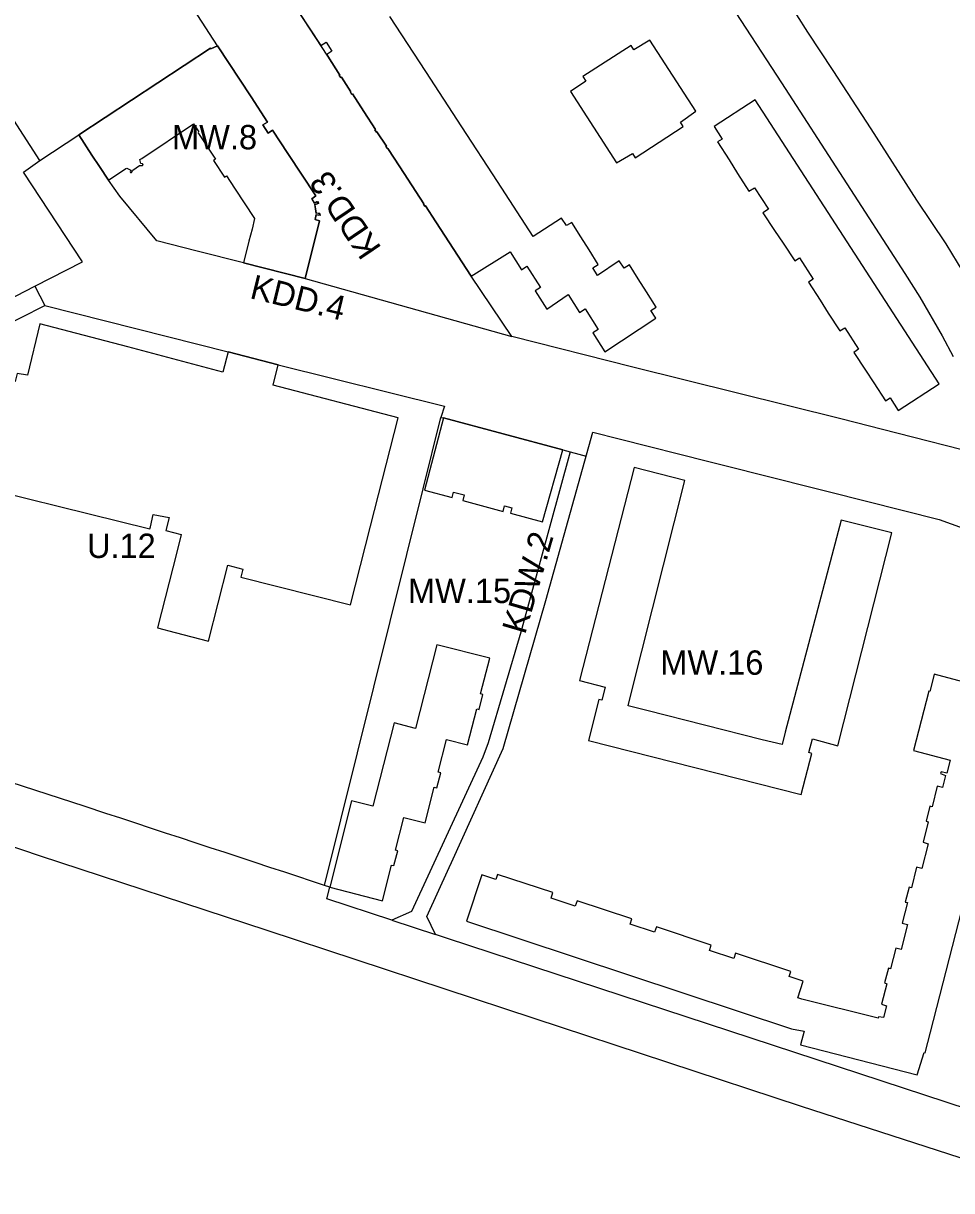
# Model space of a CAD drawing. Extents: x 7424052 to 7425705, y 5546602 to 5547569.
# Drawn here: x 7424865.9 to 7425056.7, y 5546961.1 to 5547200.9 of the extents above; entities that cross this region are included whole.
import ezdxf

# ---------------------------------------------------------------- set-up
doc = ezdxf.new("R2010")
doc.units = 0
for name, color, linetype in [('linie rozgraniczające', 7, 'Continuous'), ('nieprzekraczalne linie zabudowy', 7, 'Continuous'), ('obowiazujace linie zabudowy', 7, 'Continuous'), ('przeznaczenia terenów', 7, 'Continuous')]:
    doc.layers.add(name, color=color, linetype=linetype)

msp = doc.modelspace()

# ---------------------------------------------------------------- linework, layer by layer
at = {"layer": 'linie rozgraniczające'}
for p, q in [((7424905.84, 5547196.33), (7424884.42, 5547229.37)), ((7425007.07, 5547211.22), (7425021.71, 5547188.75)), ((7424869.3, 5547172.76), (7424848.08, 5547205.67)), ((7425027.13, 5547199.15), (7425022.42, 5547206.57)), ((7424928.48, 5547194.19), (7424921.08, 5547205.48)), ((7425032.34, 5547191.28), (7425027.13, 5547199.15)), ((7424904.48, 5547195.74), (7424905.84, 5547196.33)), ((7424905.84, 5547196.33), (7424912.72, 5547185.82)), ((7424877.35, 5547178.06), (7424904.39, 5547195.87)), ((7424904.39, 5547195.87), (7424904.48, 5547195.74)), ((7424930.98, 5547190.33), (7424928.48, 5547194.19)), ((7425040.11, 5547179.28), (7425032.34, 5547191.28)), ((7424930.85, 5547190.24), (7424930.98, 5547190.33)), ((7424931.15, 5547189.8), (7424930.85, 5547190.24)), ((7424931.28, 5547189.88), (7424931.15, 5547189.8)), ((7424933.25, 5547186.87), (7424931.28, 5547189.88)), ((7425021.71, 5547188.75), (7425047.04, 5547149.57)), ((7424933.13, 5547186.79), (7424933.25, 5547186.87)), ((7424933.43, 5547186.35), (7424933.13, 5547186.79)), ((7424933.54, 5547186.43), (7424933.43, 5547186.35)), ((7424935.91, 5547182.81), (7424933.54, 5547186.43)), ((7424912.72, 5547185.82), (7424916.07, 5547180.66)), ((7424938.28, 5547179.14), (7424935.91, 5547182.81)), ((7424916.07, 5547180.66), (7424915.16, 5547180.07)), ((7424915.16, 5547180.07), (7424916.2, 5547178.41)), ((7424938.18, 5547179.06), (7424938.28, 5547179.14)), ((7425049.53, 5547164.65), (7425040.11, 5547179.28)), ((7424869.3, 5547172.76), (7424877.35, 5547178.06)), ((7424880.02, 5547173.83), (7424877.35, 5547178.06)), ((7424916.2, 5547178.41), (7424917.12, 5547179.01)), ((7424917.12, 5547179.01), (7424920.28, 5547174.17)), ((7424938.51, 5547178.6), (7424938.18, 5547179.06)), ((7424938.59, 5547178.67), (7424938.51, 5547178.6)), ((7424940.54, 5547175.72), (7424938.59, 5547178.67)), ((7424940.44, 5547175.65), (7424940.54, 5547175.72)), ((7424940.72, 5547175.2), (7424940.44, 5547175.65)), ((7424940.84, 5547175.26), (7424940.72, 5547175.2)), ((7424943.31, 5547171.48), (7424940.84, 5547175.26)), ((7424865.92, 5547170.35), (7424869.3, 5547172.76)), ((7424881.56, 5547171.56), (7424880.02, 5547173.83)), ((7424920.28, 5547174.17), (7424926.01, 5547165.49)), ((7424878.09, 5547151.95), (7424865.92, 5547170.35)), ((7424883.45, 5547168.76), (7424881.56, 5547171.56)), ((7424948.25, 5547163.88), (7424943.31, 5547171.48)), ((7424885.76, 5547165.41), (7424883.45, 5547168.76)), ((7424893.32, 5547156.26), (7424885.76, 5547165.41)), ((7424926.01, 5547165.49), (7424925.22, 5547164.88)), ((7424925.22, 5547164.88), (7424925.69, 5547164.05)), ((7424925.69, 5547164.05), (7424926.48, 5547164.37)), ((7424926.56, 5547163.91), (7424925.81, 5547163.69)), ((7424925.81, 5547163.69), (7424926.08, 5547162.01)), ((7424926.48, 5547164.37), (7424926.56, 5547163.91)), ((7424948.16, 5547163.82), (7424948.25, 5547163.88)), ((7424948.45, 5547163.36), (7424948.16, 5547163.82)), ((7424948.55, 5547163.42), (7424948.45, 5547163.36)), ((7424950.68, 5547160.16), (7424948.55, 5547163.42)), ((7425055.55, 5547155.68), (7425049.53, 5547164.65)), ((7424926.78, 5547160.37), (7424923.86, 5547148.55)), ((7424926.1, 5547161.6), (7424925.86, 5547160.64)), ((7424925.86, 5547160.64), (7424926.78, 5547160.37)), ((7424926.08, 5547162.01), (7424926.88, 5547161.91)), ((7424926.95, 5547161.49), (7424926.1, 5547161.6)), ((7424926.88, 5547161.91), (7424926.95, 5547161.49)), ((7424957.95, 5547148.99), (7424950.68, 5547160.16)), ((7424901.65, 5547154.15), (7424893.32, 5547156.26)), ((7425060.19, 5547147.96), (7425055.55, 5547155.68)), ((7424911.17, 5547151.75), (7424901.65, 5547154.15)), ((7424868.31, 5547146.93), (7424878.09, 5547151.95)), ((7424923.86, 5547148.55), (7424911.17, 5547151.75)), ((7424923.86, 5547148.55), (7424966.29, 5547136.6)), ((7424966.29, 5547136.6), (7424957.95, 5547148.99)), ((7425047.04, 5547149.57), (7425050.12, 5547144.66)), ((7424826.56, 5547125.51), (7424868.31, 5547146.93)), ((7424868.31, 5547146.93), (7424870.34, 5547142.98)), ((7425050.12, 5547144.66), (7425054.75, 5547136.73)), ((7424828.05, 5547121.6), (7424870.34, 5547142.98)), ((7424870.34, 5547142.98), (7424908, 5547133.49)), ((7424991.15, 5547130.31), (7424966.29, 5547136.6)), ((7425054.75, 5547136.73), (7425057.01, 5547132.49)), ((7424908, 5547133.49), (7424918.29, 5547130.8)), ((7424918.29, 5547130.8), (7424952.48, 5547122.33)), ((7425033.9, 5547119.69), (7424991.15, 5547130.31)), ((7424952.48, 5547122.33), (7424951.74, 5547119.97)), ((7424948.06, 5547105.31), (7424951.74, 5547119.97)), ((7424951.74, 5547119.97), (7424952.26, 5547119.89)), ((7424952.26, 5547119.89), (7424976.75, 5547113.33)), ((7425045.42, 5547116.78), (7425033.9, 5547119.69)), ((7424973.28, 5547082.38), (7424982.92, 5547116.94)), ((7424982.92, 5547116.94), (7424988.39, 5547115.56)), ((7425062.82, 5547112.32), (7425045.42, 5547116.78)), ((7424988.39, 5547115.56), (7425006.78, 5547110.93)), ((7424978.32, 5547112.91), (7424968.16, 5547075.89)), ((7424976.75, 5547113.33), (7424981.55, 5547112.03)), ((7425006.78, 5547110.93), (7425010.05, 5547110.1)), ((7425010.05, 5547110.1), (7425028.28, 5547105.51)), ((7424927.84, 5547023.81), (7424948.06, 5547105.31)), ((7425028.28, 5547105.51), (7425031.61, 5547104.67)), ((7425031.61, 5547104.67), (7425054.11, 5547099)), ((7425054.11, 5547099), (7425059.05, 5547097.2)), ((7424964.55, 5547051.99), (7424973.28, 5547082.38)), ((7424968.16, 5547075.89), (7424961.45, 5547053.1)), ((7424878.62, 5547040.03), (7424833.77, 5547054.64)), ((7424961.45, 5547053.1), (7424960.32, 5547050.21)), ((7424960.32, 5547050.21), (7424945.7, 5547018.5)), ((7424953.9, 5547028.52), (7424964.55, 5547051.99)), ((7424882.87, 5547038.64), (7424878.62, 5547040.03)), ((7424885.95, 5547037.64), (7424882.87, 5547038.64)), ((7424889.01, 5547036.62), (7424885.95, 5547037.64)), ((7424892.07, 5547035.61), (7424889.01, 5547036.62)), ((7424895.14, 5547034.61), (7424892.07, 5547035.61)), ((7424898.2, 5547033.6), (7424895.14, 5547034.61)), ((7424901.26, 5547032.58), (7424898.2, 5547033.6)), ((7424904.33, 5547031.58), (7424901.26, 5547032.58)), ((7424907.4, 5547030.57), (7424904.33, 5547031.58)), ((7424910.46, 5547029.55), (7424907.4, 5547030.57)), ((7424913.53, 5547028.55), (7424910.46, 5547029.55)), ((7424916.58, 5547027.54), (7424913.53, 5547028.55)), ((7424953.42, 5547027.49), (7424953.9, 5547028.52)), ((7424919.65, 5547026.53), (7424916.58, 5547027.54)), ((7424927.84, 5547023.81), (7424919.65, 5547026.53)), ((7424948.87, 5547017.47), (7424953.42, 5547027.49)), ((7424928.87, 5547023.5), (7424927.84, 5547023.81)), ((7424928.26, 5547021.08), (7424928.87, 5547023.5)), ((7424941.61, 5547016.7), (7424928.26, 5547021.08)), ((7424945.7, 5547018.5), (7424941.61, 5547016.7)), ((7424941.61, 5547016.7), (7424950.6, 5547013.76)), ((7424950.6, 5547013.76), (7424948.87, 5547017.47)), ((7424953.05, 5547012.95), (7424950.6, 5547013.76)), ((7425060.14, 5546977.83), (7424953.05, 5547012.95))]:
    msp.add_line(p, q, dxfattribs=at)
msp.add_lwpolyline([(7425057.52, 5546865.73), (7425063.89, 5546961.78), (7425060.73, 5546967.11), (7425025.83, 5546978.44), (7424970.91, 5546996.51), (7424916, 5547014.59), (7424869.23, 5547029.94), (7424833.88, 5547041.92)], dxfattribs=at)
at = {"layer": 'nieprzekraczalne linie zabudowy'}
for p, q in [((7424906.94, 5547129.31), (7424887.39, 5547134.46)), ((7424908, 5547133.49), (7424906.94, 5547129.31)), ((7424918.29, 5547130.8), (7424908, 5547133.49)), ((7424917.24, 5547126.62), (7424918.29, 5547130.8)), ((7424942.93, 5547119.9), (7424917.24, 5547126.62)), ((7424937.27, 5547097.62), (7424942.93, 5547119.9))]:
    msp.add_line(p, q, dxfattribs=at)
at = {"layer": 'obowiazujace linie zabudowy'}
for p, q in [((7424922.55, 5547203.23), (7424927.05, 5547196.38)), ((7424948.65, 5547191.04), (7424941.21, 5547202.37)), ((7424927.05, 5547196.38), (7424928.12, 5547197.06)), ((7424928.12, 5547197.06), (7424929.33, 5547195.21)), ((7424929.33, 5547195.21), (7424928.27, 5547194.51)), ((7424928.27, 5547194.51), (7424928.48, 5547194.19)), ((7424928.48, 5547194.19), (7424930.98, 5547190.33)), ((7424930.98, 5547190.33), (7424930.85, 5547190.24)), ((7424930.85, 5547190.24), (7424931.15, 5547189.8)), ((7424931.15, 5547189.8), (7424931.28, 5547189.88)), ((7424931.28, 5547189.88), (7424933.25, 5547186.87)), ((7424956.03, 5547179.7), (7424948.65, 5547191.04)), ((7424933.25, 5547186.87), (7424933.13, 5547186.79)), ((7424933.13, 5547186.79), (7424933.43, 5547186.35)), ((7424933.43, 5547186.35), (7424933.54, 5547186.43)), ((7424933.54, 5547186.43), (7424935.91, 5547182.81)), ((7424935.91, 5547182.81), (7424938.28, 5547179.14)), ((7424938.28, 5547179.14), (7424938.18, 5547179.06)), ((7424963.33, 5547168.47), (7424956.03, 5547179.7)), ((7424938.18, 5547179.06), (7424938.51, 5547178.6)), ((7424938.51, 5547178.6), (7424938.59, 5547178.67)), ((7424938.59, 5547178.67), (7424940.54, 5547175.72)), ((7424940.54, 5547175.72), (7424940.44, 5547175.65)), ((7424940.44, 5547175.65), (7424940.72, 5547175.2)), ((7424940.72, 5547175.2), (7424940.84, 5547175.26)), ((7424940.84, 5547175.26), (7424943.31, 5547171.48)), ((7424943.31, 5547171.48), (7424948.25, 5547163.88)), ((7424970.7, 5547157.14), (7424963.33, 5547168.47)), ((7424948.25, 5547163.88), (7424948.16, 5547163.82)), ((7424948.16, 5547163.82), (7424948.45, 5547163.36)), ((7424948.45, 5547163.36), (7424948.55, 5547163.42)), ((7424948.55, 5547163.42), (7424950.68, 5547160.16)), ((7424950.68, 5547160.16), (7424957.95, 5547148.99)), ((7424976.49, 5547160.95), (7424970.7, 5547157.14)), ((7424977.51, 5547159.38), (7424976.49, 5547160.95)), ((7424978.62, 5547160.03), (7424977.51, 5547159.38)), ((7424980.48, 5547157.1), (7424978.62, 5547160.03)), ((7424982.18, 5547154.39), (7424980.48, 5547157.1)), ((7424957.95, 5547148.99), (7424965.95, 5547154.02)), ((7424965.95, 5547154.02), (7424968.31, 5547150.33)), ((7424984.06, 5547151.39), (7424982.18, 5547154.39)), ((7424968.31, 5547150.33), (7424969.4, 5547151.04)), ((7424969.4, 5547151.04), (7424972.2, 5547146.68)), ((7424982.96, 5547150.69), (7424984.06, 5547151.39)), ((7424983.92, 5547149.17), (7424982.96, 5547150.69)), ((7424988.37, 5547152.18), (7424983.92, 5547149.17)), ((7424989.39, 5547150.62), (7424988.37, 5547152.18)), ((7424990.5, 5547151.3), (7424989.39, 5547150.62)), ((7424992.28, 5547148.49), (7424990.5, 5547151.3)), ((7424994, 5547145.79), (7424992.28, 5547148.49)), ((7424972.2, 5547146.68), (7424971.09, 5547145.99)), ((7424971.09, 5547145.99), (7424973.49, 5547142.24)), ((7424995.98, 5547142.66), (7424994, 5547145.79)), ((7424973.49, 5547142.24), (7424977.9, 5547145.23)), ((7424977.9, 5547145.23), (7424980.24, 5547141.57)), ((7424980.24, 5547141.57), (7424981.34, 5547142.28)), ((7424981.34, 5547142.28), (7424984.05, 5547138.05)), ((7424994.89, 5547141.98), (7424995.98, 5547142.66)), ((7424995.92, 5547140.38), (7424994.89, 5547141.98)), ((7424985.42, 5547133.49), (7424995.92, 5547140.38)), ((7424984.05, 5547138.05), (7424982.95, 5547137.35)), ((7424982.95, 5547137.35), (7424985.42, 5547133.49)), ((7424991.46, 5547109.67), (7424980.18, 5547065.93)), ((7425001.86, 5547107.06), (7424991.46, 5547109.67)), ((7424990.84, 5547063.3), (7425001.86, 5547107.06)), ((7425033.98, 5547098.89), (7425022.49, 5547055.35)), ((7425044.38, 5547096.29), (7425033.98, 5547098.89)), ((7425033.29, 5547052.53), (7425044.38, 5547096.29)), ((7424950.88, 5547073.28), (7424946.48, 5547056.1)), ((7424961.76, 5547070.54), (7424950.88, 5547073.28)), ((7424959.87, 5547063.2), (7424961.76, 5547070.54)), ((7425053.06, 5547067.21), (7425052.25, 5547063.91)), ((7425070.24, 5547062.67), (7425053.06, 5547067.21)), ((7424980.18, 5547065.93), (7424985.49, 5547064.57)), ((7424985.49, 5547064.57), (7424984.81, 5547061.87)), ((7424959.57, 5547059.98), (7424960.37, 5547063.05)), ((7424960.37, 5547063.05), (7424959.87, 5547063.2)), ((7424984.18, 5547062.04), (7424982.04, 5547053.6)), ((7424984.81, 5547061.87), (7424984.18, 5547062.04)), ((7424990.18, 5547060.73), (7424990.84, 5547063.3)), ((7425051.99, 5547063.73), (7425048.83, 5547051.53)), ((7425052.19, 5547063.68), (7425051.99, 5547063.73)), ((7425052.25, 5547063.91), (7425052.19, 5547063.68)), ((7424957.19, 5547052.75), (7424959.08, 5547060.1)), ((7424959.08, 5547060.1), (7424959.57, 5547059.98)), ((7424994.06, 5547059.75), (7424990.18, 5547060.73)), ((7425017.74, 5547053.77), (7424994.06, 5547059.75)), ((7424942.13, 5547057.25), (7424937.74, 5547040.09)), ((7424946.48, 5547056.1), (7424942.13, 5547057.25)), ((7425022.49, 5547055.35), (7425021.84, 5547052.77)), ((7424951.15, 5547047.14), (7424952.88, 5547053.83)), ((7424952.88, 5547053.83), (7424957.19, 5547052.75)), ((7424982.04, 5547053.6), (7425025.79, 5547042.51)), ((7425021.84, 5547052.77), (7425017.74, 5547053.77)), ((7425027.36, 5547051.12), (7425028.06, 5547053.94)), ((7425028.06, 5547053.94), (7425033.29, 5547052.53)), ((7425025.79, 5547042.51), (7425027.92, 5547050.97)), ((7425027.92, 5547050.97), (7425027.36, 5547051.12)), ((7425048.83, 5547051.53), (7425056.36, 5547049.56)), ((7425056.36, 5547049.56), (7425055.7, 5547046.9)), ((7424950.87, 5547043.9), (7424951.68, 5547046.98)), ((7424951.68, 5547046.98), (7424951.15, 5547047.14)), ((7425054.51, 5547047.21), (7425054.4, 5547046.8)), ((7425054.4, 5547046.8), (7425055.42, 5547046.39)), ((7425055.7, 5547046.9), (7425054.51, 5547047.21)), ((7425055.42, 5547046.39), (7425054.79, 5547043.95)), ((7424948.46, 5547036.73), (7424950.35, 5547044.05)), ((7424950.35, 5547044.05), (7424950.87, 5547043.9)), ((7425052.32, 5546993.68), (7425065.32, 5547044.44)), ((7425053.74, 5547044.21), (7425052.67, 5547040)), ((7425054.79, 5547043.95), (7425053.74, 5547044.21)), ((7424933.35, 5547041.22), (7424928.87, 5547023.5)), ((7424937.74, 5547040.09), (7424933.35, 5547041.22)), ((7425052.18, 5547040.09), (7425051.42, 5547037.05)), ((7425052.67, 5547040), (7425052.18, 5547040.09)), ((7424942.38, 5547031.07), (7424944.11, 5547037.82)), ((7424944.11, 5547037.82), (7424948.46, 5547036.73)), ((7425051.88, 5547036.93), (7425050.8, 5547032.7)), ((7425051.42, 5547037.05), (7425051.88, 5547036.93)), ((7424942.05, 5547027.93), (7424942.88, 5547030.95)), ((7424942.88, 5547030.95), (7424942.38, 5547031.07)), ((7425051.88, 5547032.41), (7425050.57, 5547027.29)), ((7425050.8, 5547032.7), (7425051.88, 5547032.41)), ((7424939.71, 5547020.68), (7424941.6, 5547028.03)), ((7424941.6, 5547028.03), (7424942.05, 5547027.93)), ((7424960.14, 5547026), (7424956.96, 5547016.48)), ((7424963.02, 5547025.04), (7424960.14, 5547026)), ((7424963.38, 5547026.11), (7424963.02, 5547025.04)), ((7424974.7, 5547022.36), (7424963.38, 5547026.11)), ((7425049.48, 5547027.56), (7425048.4, 5547023.34)), ((7425050.57, 5547027.29), (7425049.48, 5547027.56)), ((7424928.87, 5547023.5), (7424939.71, 5547020.68)), ((7425047.94, 5547023.45), (7425047.14, 5547020.4)), ((7425048.4, 5547023.34), (7425047.94, 5547023.45)), ((7424974.36, 5547021.25), (7424974.7, 5547022.36)), ((7424979.34, 5547019.61), (7424974.36, 5547021.25)), ((7424979.73, 5547020.7), (7424979.34, 5547019.61)), ((7424990.99, 5547016.98), (7424979.73, 5547020.7)), ((7425047.62, 5547020.3), (7425046.54, 5547016.08)), ((7425047.14, 5547020.4), (7425047.62, 5547020.3)), ((7424956.96, 5547016.48), (7425023.76, 5546994.38)), ((7424990.64, 5547015.88), (7424990.99, 5547016.98)), ((7425046.54, 5547016.08), (7425047.63, 5547015.79)), ((7424995.62, 5547014.22), (7424990.64, 5547015.88)), ((7424996, 5547015.32), (7424995.62, 5547014.22)), ((7425007.29, 5547011.59), (7424996, 5547015.32)), ((7425047.63, 5547015.79), (7425046.33, 5547010.69)), ((7425006.91, 5547010.49), (7425007.29, 5547011.59)), ((7425011.92, 5547008.85), (7425006.91, 5547010.49)), ((7425012.29, 5547009.93), (7425011.92, 5547008.85)), ((7425023.61, 5547006.19), (7425012.29, 5547009.93)), ((7425045.23, 5547010.96), (7425044.15, 5547006.72)), ((7425046.33, 5547010.69), (7425045.23, 5547010.96)), ((7425043.68, 5547006.83), (7425042.9, 5547003.8)), ((7425044.15, 5547006.72), (7425043.68, 5547006.83)), ((7425023.31, 5547005.14), (7425023.61, 5547006.19)), ((7425026.17, 5547004.16), (7425023.31, 5547005.14)), ((7425025.05, 5547000.75), (7425026.17, 5547004.16)), ((7425043.36, 5547003.64), (7425042.28, 5546999.43)), ((7425042.9, 5547003.8), (7425043.36, 5547003.64)), ((7425025.92, 5547000.49), (7425025.05, 5547000.75)), ((7425041.55, 5546996.56), (7425025.92, 5547000.49)), ((7425042.28, 5546999.43), (7425043.31, 5546999.12)), ((7425043.31, 5546999.12), (7425042.67, 5546996.71)), ((7425041.62, 5546996.83), (7425041.55, 5546996.56)), ((7425042.67, 5546996.71), (7425041.62, 5546996.83)), ((7425023.76, 5546994.38), (7425026.41, 5546993.92)), ((7425026.41, 5546993.92), (7425025.64, 5546991.1)), ((7425051.25, 5546989.43), (7425052.32, 5546993.68)), ((7425025.64, 5546991.1), (7425049.62, 5546984.96)), ((7425049.62, 5546984.96), (7425051.01, 5546989.49)), ((7425051.01, 5546989.49), (7425051.25, 5546989.43))]:
    msp.add_line(p, q, dxfattribs=at)
for points in [[(7424901.77, 5547178.55), (7424905.39, 5547173.03), (7424905.01, 5547172.76), (7424907.26, 5547169.34), (7424907.64, 5547169.59), (7424909.33, 5547167.1), (7424913.39, 5547160.82), (7424912.91, 5547158.67), (7424912.27, 5547156.17), (7424911.17, 5547151.75), (7424923.86, 5547148.55), (7424926.78, 5547160.37), (7424925.86, 5547160.64), (7424926.12, 5547161.67), (7424926.65, 5547161.53), (7424926.84, 5547161.73), (7424926.7, 5547161.93), (7424926.11, 5547161.85), (7424925.8, 5547163.78), (7424926.33, 5547163.85), (7424926.43, 5547164.18), (7424926.18, 5547164.25), (7424925.74, 5547163.96), (7424925.22, 5547164.88), (7424926.01, 5547165.49), (7424920.28, 5547174.17), (7424917.12, 5547179.01), (7424916.2, 5547178.41), (7424915.16, 5547180.07), (7424916.07, 5547180.66), (7424912.72, 5547185.82), (7424905.84, 5547196.33), (7424904.48, 5547195.74), (7424904.39, 5547195.87), (7424877.35, 5547178.06), (7424880.02, 5547173.83), (7424881.56, 5547171.56), (7424883.45, 5547168.76), (7424887.01, 5547171.12), (7424887.2, 5547171.22), (7424887.99, 5547170.78), (7424887.87, 5547170.45), (7424887.96, 5547170.27), (7424888.17, 5547170.33), (7424888.39, 5547170.8), (7424889.82, 5547171.74), (7424890.38, 5547171.75), (7424890.51, 5547171.94), (7424890.42, 5547172.11), (7424890.08, 5547172.13), (7424889.87, 5547172.98), (7424890.24, 5547173.21), (7424900.88, 5547180.27), (7424901.95, 5547178.67)], [(7424978.33, 5547186.93), (7424987.8, 5547172.26), (7424991.07, 5547174.2), (7424991.64, 5547173.3), (7425001.53, 5547179.78), (7425000.95, 5547180.65), (7425004.11, 5547182.87), (7424994.67, 5547197.48), (7424991.36, 5547195.52), (7424990.8, 5547196.4), (7424980.9, 5547189.99), (7424981.49, 5547189.09), (7424978.33, 5547186.93)], [(7425007.87, 5547179.75), (7425009.54, 5547177.15), (7425008.59, 5547176.58), (7425010.96, 5547172.89), (7425012.69, 5547170.11), (7425015.03, 5547166.48), (7425016.2, 5547167.18), (7425019.03, 5547162.77), (7425017.9, 5547162.04), (7425020.27, 5547158.38), (7425022.09, 5547155.79), (7425024.45, 5547152.13), (7425025.39, 5547152.78), (7425028.25, 5547148.41), (7425027.26, 5547147.78), (7425029.66, 5547144.06), (7425031.34, 5547141.43), (7425033.73, 5547137.75), (7425034.73, 5547138.4), (7425037.54, 5547134.03), (7425036.59, 5547133.35), (7425038.95, 5547129.7), (7425040.68, 5547127.08), (7425043.08, 5547123.4), (7425044.02, 5547123.99), (7425045.68, 5547121.43), (7425054.15, 5547126.9), (7425016.3, 5547185.26), (7425007.87, 5547179.75)], [(7424887.39, 5547134.46), (7424869.33, 5547139.19), (7424866.8, 5547128.69), (7424864.65, 5547129.03), (7424864.24, 5547127.34), (7424853.51, 5547129.93), (7424848.1, 5547107.91), (7424891.9, 5547097.08), (7424892.02, 5547097.52), (7424892.6, 5547100.01), (7424895.88, 5547099.43), (7424895.17, 5547096.76), (7424898.36, 5547095.95), (7424897.45, 5547092.28), (7424893.47, 5547076.73), (7424897.15, 5547075.81), (7424903.99, 5547074.05), (7424907.97, 5547089.61), (7424911.02, 5547088.78), (7424910.64, 5547087.2), (7424933.17, 5547081.48), (7424937.27, 5547097.62)], [(7424952.26, 5547119.89), (7424948.36, 5547105.04), (7424954.03, 5547103.51), (7424954.33, 5547104.61), (7424956.53, 5547104.07), (7424956.25, 5547102.92), (7424964.52, 5547100.69), (7424964.81, 5547101.81), (7424966.29, 5547101.44), (7424966, 5547100.29), (7424972.6, 5547098.51), (7424976.75, 5547113.33), (7424952.26, 5547119.89)]]:
    msp.add_lwpolyline(points, dxfattribs=at)

# ---------------------------------------------------------------- texts
at = {"layer": 'przeznaczenia terenów'}
for s, p in [('MW.8', (7424896.49, 5547175.06)), ('U.12', (7424879, 5547091.11)), ('MW.15', (7424944.97, 5547081.85)), ('MW.16', (7424996.82, 5547067.12))]:
    msp.add_text(s, height=5, dxfattribs=at).set_placement(p)
for s, rotation, p in [('KDD.3', 124.1057, (7424939.63, 5547154.78)), ('KDD.4', 346.2242, (7424912.26, 5547144.53)), ('KDW.2', 73.7874, (7424969.02, 5547075.23))]:
    msp.add_text(s, height=5, rotation=rotation, dxfattribs=at).set_placement(p)

doc.saveas('drawing.dxf')
